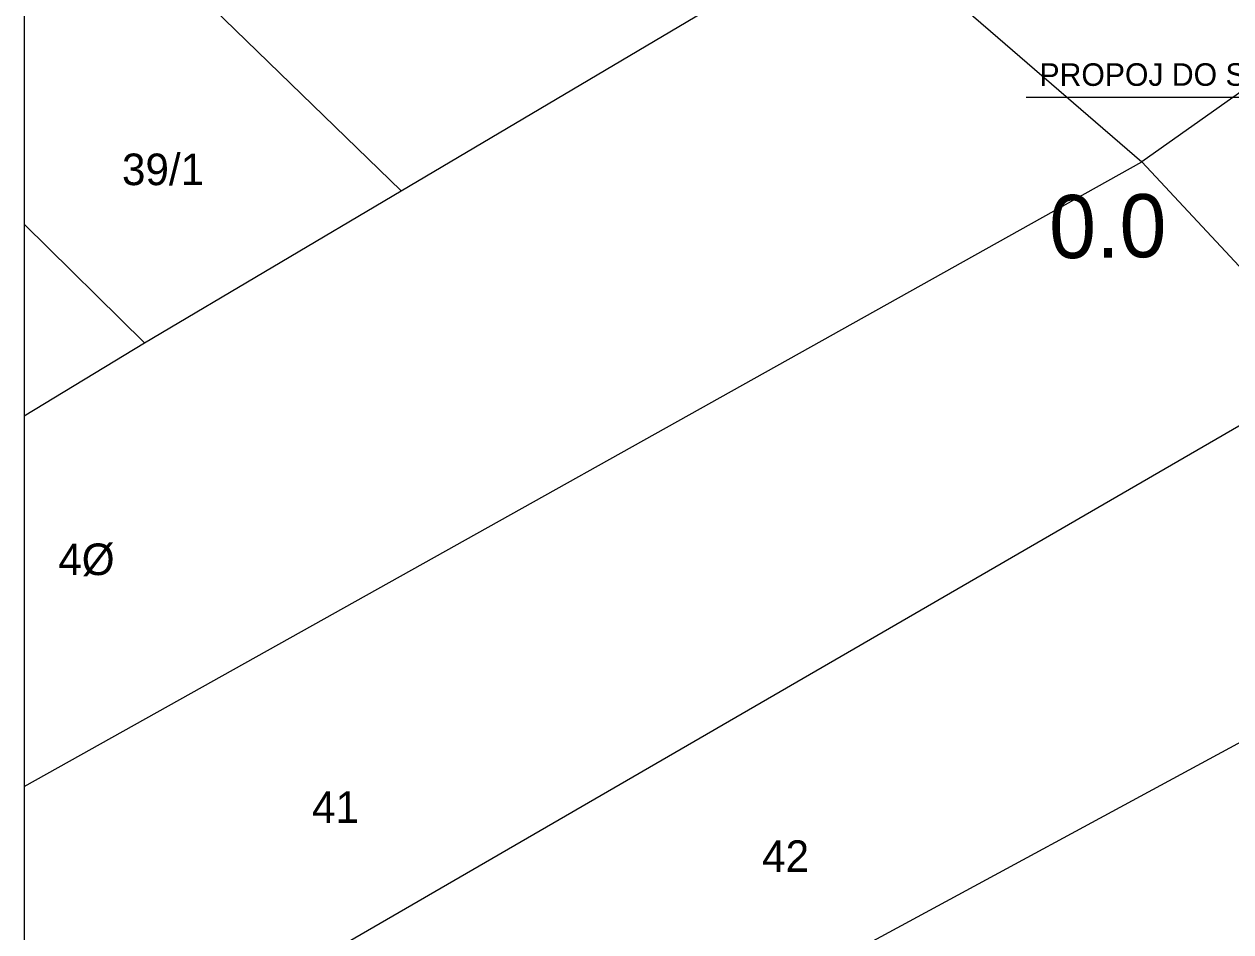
# Model space of a CAD drawing. Extents: x -643342 to -638635, y -1201752 to -1189948.
# Drawn here: x -639640.6 to -639573.7, y -1192781.6 to -1192731.3 of the extents above; entities that cross this region are included whole.
import ezdxf

# ---------------------------------------------------------------- set-up
doc = ezdxf.new("R2010")
doc.units = 0
for name, color, linetype in [('42', 7, 'Continuous'), ('K-HRANICE_KN', 7, 'Continuous'), ('K-ČÍSLA_PARCEL', 7, 'Continuous'), ('N-SO101_HECTOMETRY', 7, 'Continuous'), ('tomaštík - Džuganovi - Vrstva 36', 7, 'Continuous'), ('Vrstva 13', 7, 'Continuous')]:
    doc.layers.add(name, color=color, linetype=linetype)

msp = doc.modelspace()

# ---------------------------------------------------------------- linework, layer by layer
at = {"layer": '42'}
msp.add_line((-639531.387, -1192735.397), (-639585.033, -1192735.397), dxfattribs=at)
at = {"layer": 'K-HRANICE_KN'}
for p, q in [((-639619.69, -1192740.58), (-639594.22, -1192725.5)), ((-639591.6, -1192727.76), (-639578.63, -1192738.96)), ((-639630.73, -1192729.86), (-639619.69, -1192740.58)), ((-639567.94, -1192731.4), (-639578.63, -1192738.96)), ((-639640.591, -1192773.577), (-639578.63, -1192738.96)), ((-639578.63, -1192738.96), (-639567.88, -1192750.5)), ((-639633.92, -1192749), (-639619.69, -1192740.58)), ((-639633.92, -1192749), (-639640.591, -1192742.427)), ((-639640.591, -1192753.038), (-639633.92, -1192749)), ((-639567.88, -1192750.5), (-639640.591, -1192792.591)), ((-639558.48, -1192763.2), (-639614.547, -1192793.496))]:
    msp.add_line(p, q, dxfattribs=at)
at = {"layer": 'Vrstva 13'}
msp.add_lwpolyline([(-639343.591, -1192858.606), (-639343.591, -1192648.606), (-639640.591, -1192648.606), (-639640.591, -1192858.606), (-639343.591, -1192858.606)], dxfattribs=at)

# ---------------------------------------------------------------- texts
at = {"layer": 'K-ČÍSLA_PARCEL'}
for s, p in [('39/1', (-639635.167, -1192740.26)), ('4%%c', (-639638.698, -1192761.87)), ('41', (-639624.632, -1192775.6)), ('42', (-639599.677, -1192778.32))]:
    msp.add_text(s, height=1.75, dxfattribs=at).set_placement(p)
at = {"layer": 'N-SO101_HECTOMETRY'}
msp.add_text('0.0', height=3.5, rotation=0.68952, dxfattribs=at).set_placement((-639583.746, -1192744.32))
at = {"layer": 'tomaštík - Džuganovi - Vrstva 36'}
msp.add_text('PROPOJ DO STÁVAJÍCÍHO STL PLYNOVODU PE d 110', height=1.25, rotation=0.03066, dxfattribs=at).set_placement((-639584.298, -1192734.76))

doc.saveas('drawing.dxf')
